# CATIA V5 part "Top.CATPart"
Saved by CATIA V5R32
Part number: Part1.1
Bounding box of the stored display mesh (mm): x -50 to 50, y -25 to 25, z -20 to 0
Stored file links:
  D:\PROJECTS\Project 2022\CATIA V5 6R 2022\Resources\Part Files\c12_catia_v5_6r2022_prt\c12_catia_v5-6r2022 figr_12-8\Top.CATPart
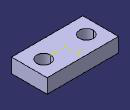
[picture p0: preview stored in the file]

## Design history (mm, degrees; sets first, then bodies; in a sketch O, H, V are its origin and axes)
Body1 (main body)
  Sketch1 on xy-plane, origin (0, 0, 0), H (1, 0, 0), V (0, 1, 0)
    line L1 (50, 25) -> (50, -25)
    line L2 (50, -25) -> (-50, -25)
    line L3 (-50, -25) -> (-50, 25)
    line L4 (-50, 25) -> (50, 25)
    circle A1 centre (-30, 0) radius 10
    point P5 (-30, 0)
    circle A2 centre (30, 0) radius 10
    length L2 = 100
    length L1 = 50
    radius A1 = 10
    distance P5 V = 30
    vertical: L1 V, L3 V
    horizontal: L2 H, L4 H
    equidistance: L1 L3 O, L2 L4 O
    coincidence: P5 H
    symmetry: A1 A2 V
  Pad1: profile Sketch1, direction (0, 0, -1), length 20
  Sketch2 on face of Pad1, origin (0, 0, 0), H (1, 0, 0), V (0, 1, 0)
